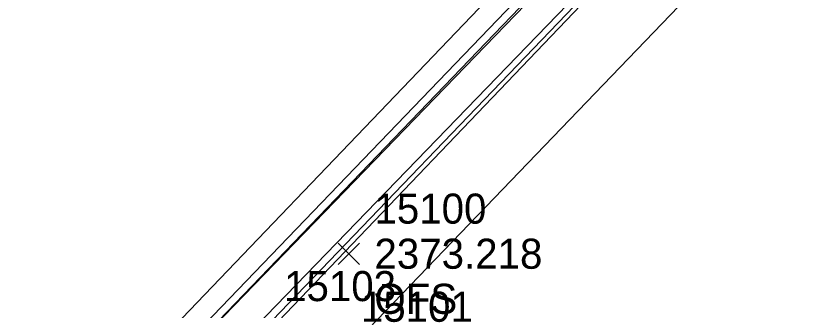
# Model space of a CAD drawing. Extents: x 2377639 to 2379738, y 729875 to 732734.
# Drawn here: x 2378184.5 to 2378237.4, y 730348.5 to 730368 of the extents above; entities that cross this region are included whole.
import ezdxf

# ---------------------------------------------------------------- set-up
doc = ezdxf.new("R2010")
doc.units = 0
for name, color, linetype in [('TOPO_CURBGTR_Back-of-Curb', 7, 'Continuous'), ('TOPO_CURBGTR_Face-of-Curb', 7, 'Continuous'), ('TOPO_CURBGTR_Lip-of-Gutter', 7, 'Continuous'), ('TOPO_DATA_Elevations', 7, 'Continuous'), ('TOPO_LNDSCP_Misc', 7, 'Continuous'), ('TOPO_STORM_Line-Other', 7, 'Continuous'), ('TOPO_SW_Back', 7, 'Continuous')]:
    doc.layers.add(name, color=color, linetype=linetype)

msp = doc.modelspace()

# ---------------------------------------------------------------- linework, layer by layer
at = {"layer": 'TOPO_CURBGTR_Back-of-Curb'}
msp.add_lwpolyline([(2378186.074, 730334.914), (2378191.856, 730341.368), (2378266.293, 730418.911), (2378294.595, 730448.487), (2378365.126, 730522.117)], dxfattribs=at)
at = {"layer": 'TOPO_CURBGTR_Face-of-Curb'}
msp.add_lwpolyline([(2378185.703, 730335.249), (2378191.489, 730341.708), (2378265.932, 730419.257), (2378294.234, 730448.833), (2378364.765, 730522.463)], dxfattribs=at)
at = {"layer": 'TOPO_CURBGTR_Lip-of-Gutter'}
msp.add_lwpolyline([(2378184.516, 730336.464), (2378190.481, 730342.622), (2378264.806, 730420.319), (2378293.203, 730449.965), (2378361.377, 730521.001)], dxfattribs=at)
at = {"layer": 'TOPO_DATA_Elevations'}
for p, q in [((2378205.913, 730351.494), (2378207.327, 730352.908)), ((2378205.913, 730352.908), (2378207.327, 730351.494))]:
    msp.add_line(p, q, dxfattribs=at)
at = {"layer": 'TOPO_LNDSCP_Misc'}
msp.add_lwpolyline([(2378191.67, 730341.16), (2378267.071, 730419.195), (2378268.514, 730417.801), (2378193.113, 730339.766)], close=True, dxfattribs=at)
at = {"layer": 'TOPO_STORM_Line-Other'}
for q in [(2378186.996, 730332.08), (2378188.378, 730333.526)]:
    msp.add_line((2378608.313, 730773.027), q, dxfattribs=at)
at = {"layer": 'TOPO_SW_Back'}
for p, q in [((2378193.653, 730339.54), (2378269.741, 730418.894)), ((2378199.093, 730338.02), (2378268.614, 730410.409))]:
    msp.add_line(p, q, dxfattribs=at)

# ---------------------------------------------------------------- texts
at = {"layer": 'TOPO_DATA_Elevations'}
for s, p in [('15100', (2378208.327, 730354.201)), ('2373.218', (2378208.327, 730351.201)), ('15103', (2378202.326, 730349.047)), ('OFS', (2378208.327, 730348.201)), ('15101', (2378207.425, 730347.673))]:
    msp.add_text(s, height=2, dxfattribs=at).set_placement(p)

doc.saveas('drawing.dxf')
